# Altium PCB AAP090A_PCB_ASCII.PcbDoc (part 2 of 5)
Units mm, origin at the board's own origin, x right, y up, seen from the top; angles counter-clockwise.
Board outline 160 x 130 mm, 4 copper layers (Top Layer, Signal Layer 1, Signal Layer 2, Bottom Layer), stack 1.567 mm thick; 507 components, 275 nets, 1462 pads, 1041 vias.
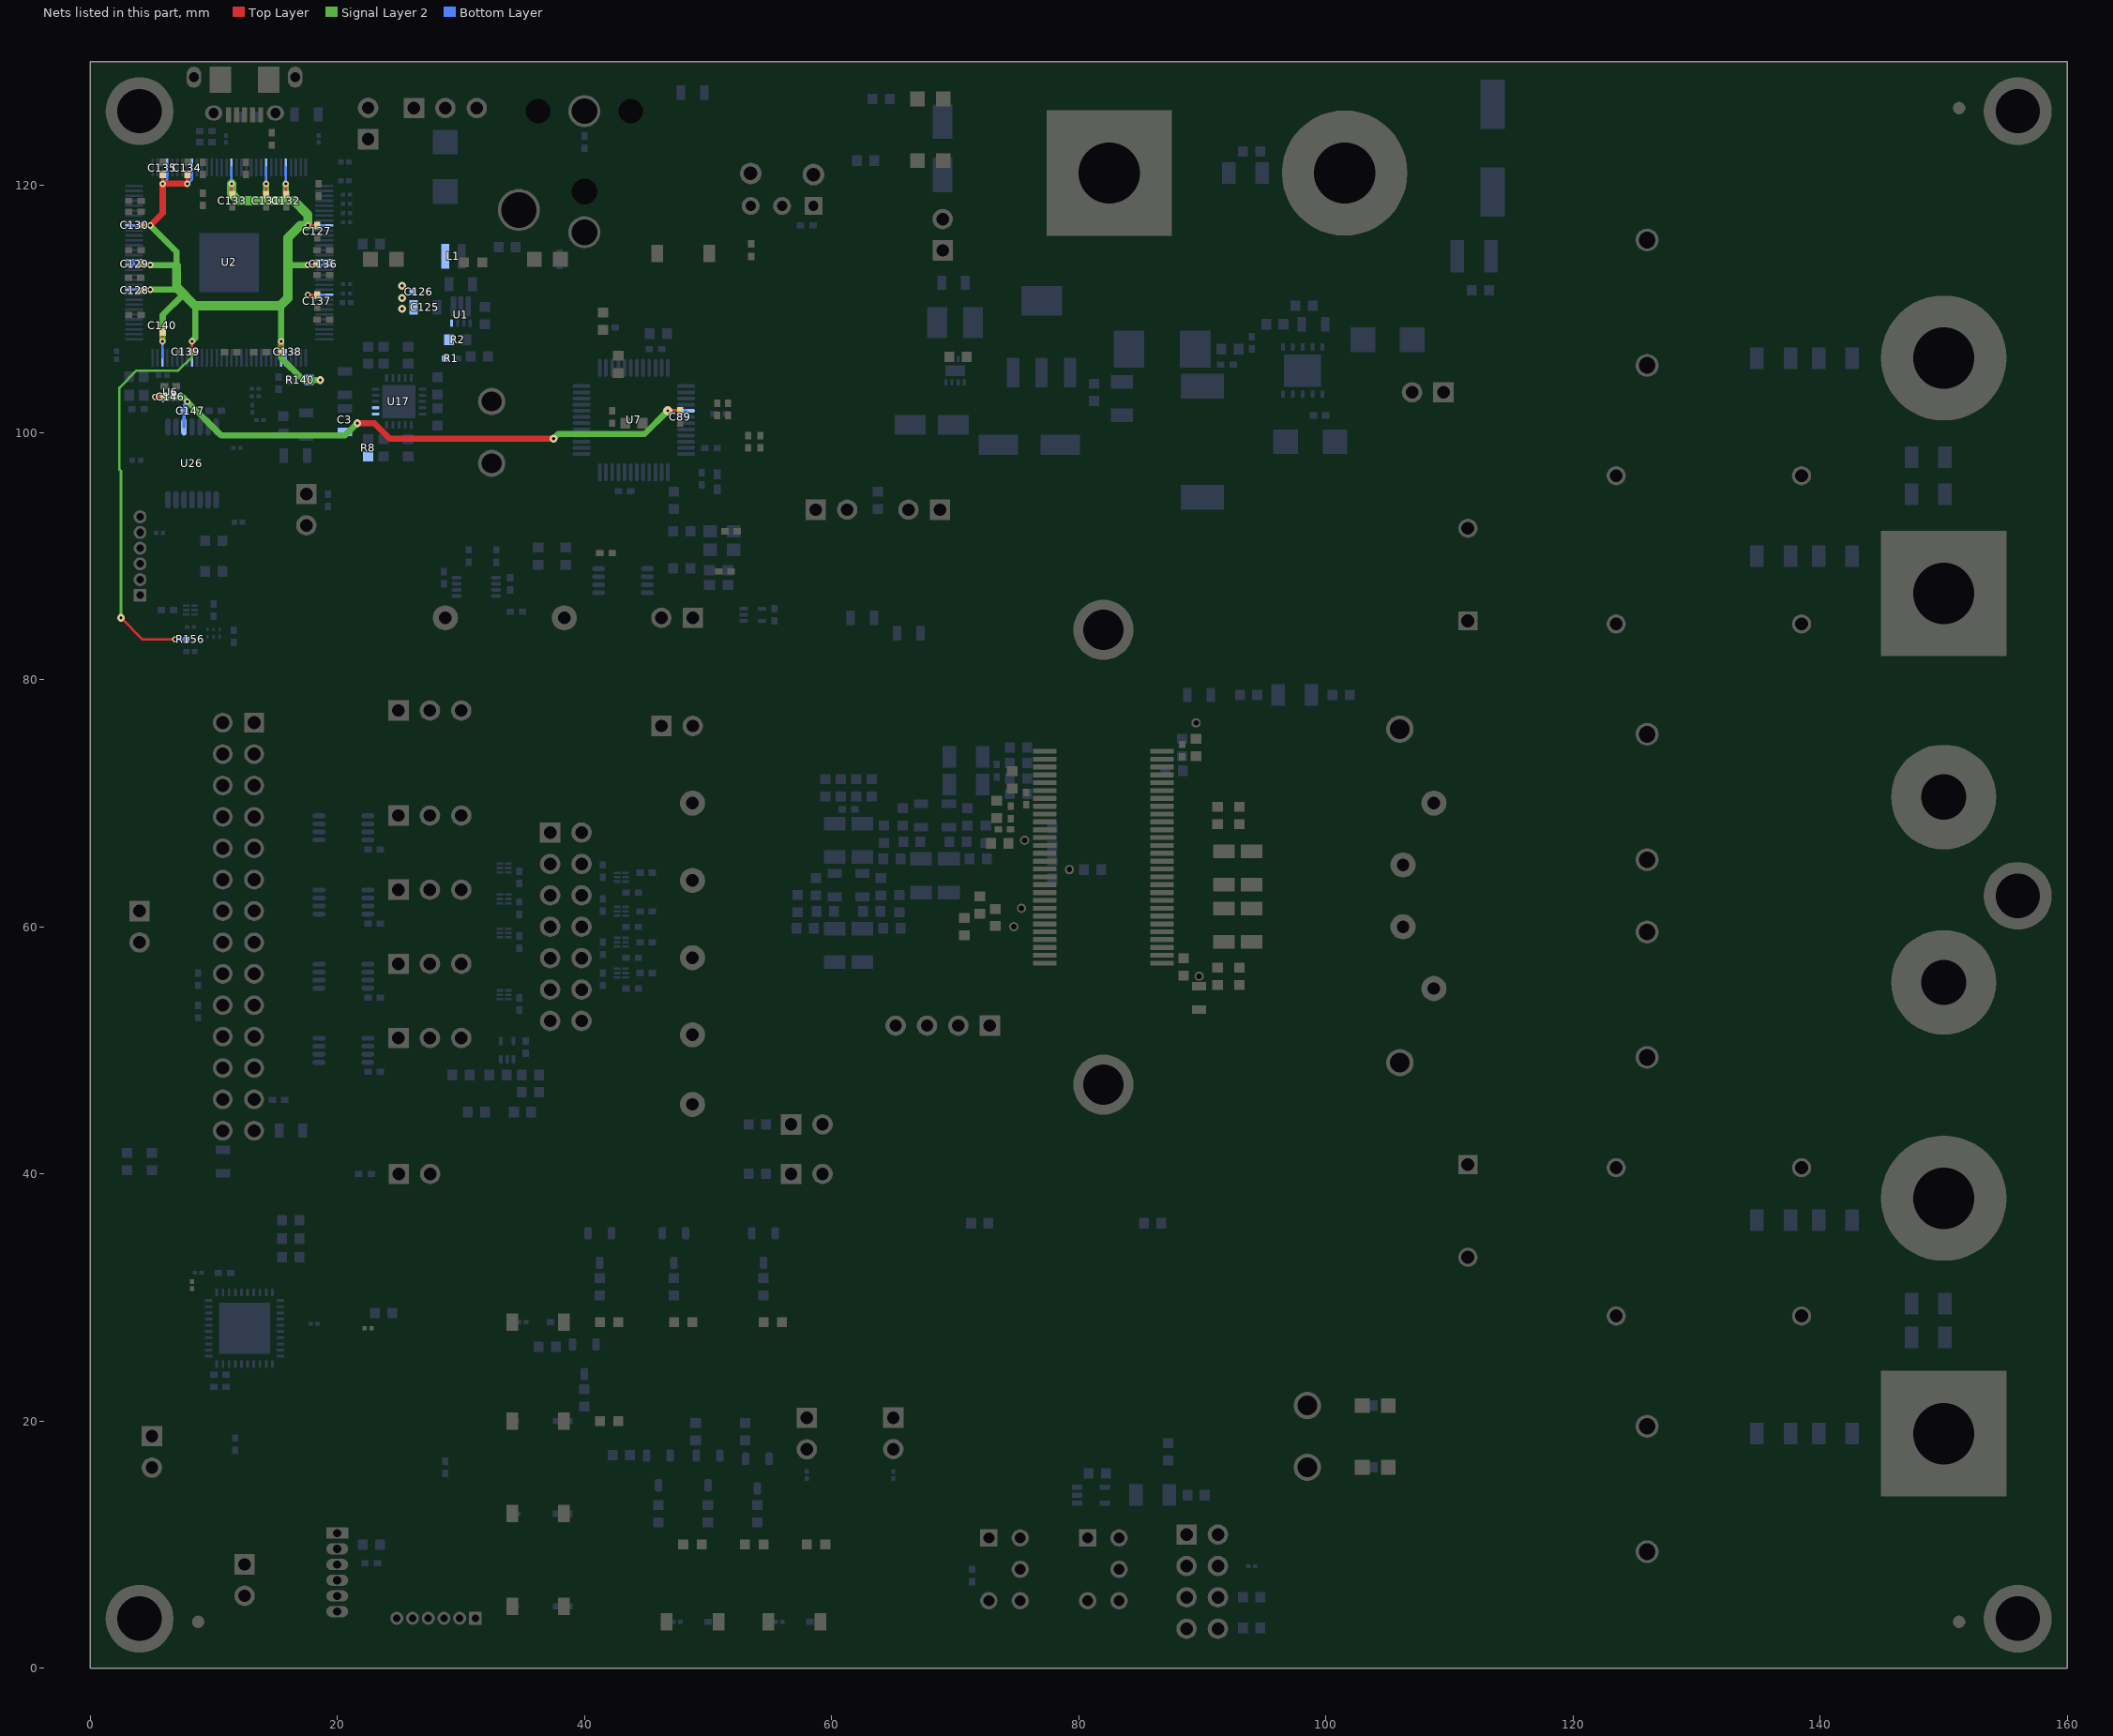
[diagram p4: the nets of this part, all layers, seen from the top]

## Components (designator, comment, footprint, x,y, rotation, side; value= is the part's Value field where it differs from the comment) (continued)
R159 "RC0805JR-070RL" 0805_KTR 17.5,100.625 r270 bottom
R160 "DNP" 0201L 20.75,112 r180 bottom
R161 "DNP" 0201L 20.75,111.25 r180 bottom
R162 "DNP" 0201L 13.375,103.545 r180 bottom
R163 "DNP" 0201L 13.375,102.92 r180 bottom
R164 "RC0805JR-070RL" 0805_KTR 16.625,98.125 r180 bottom
R165 "ERJ-3GEY0R00V" 0603L 88.375,74.5 r90 bottom
R166 "DNP" 0603L 87.75,72.625 r0 bottom
R167 "DNP" 0603L 15.625,100.625 r270 bottom
R168 "ERJ-3GEY0R00V" 0603L 35,45 r0 bottom
R169 "ERJ-3GEY0R00V" 0603L 38.5,90 r90 bottom
R170 "ERJ-3GEY0R00V" 0603L 36.25,90 r90 bottom
S1 "DAC MUTE" SW_200USP1T1A1M2 74,8 r0 top
S2 "SPDIF-RESET" SW_TL1015AF160QG 48,114.5 r0 top
S3 "AMP RESET" SW_200USP1T1A1M2 82,8 r0 top
S4 "MUTE" SW_TL1015AF160QG 36.25,20 r180 top
S5 "VOL UP" SW_TL1015AF160QG 36.25,12.5 r180 top
S6 "VOL DN" SW_TL1015AF160QG 36.25,5 r180 top
S7 "PROGRAM SEL" SW_TL1015AF160QG 57,3.75 r180 top
S8 "LOAD" SW_TL1015AF160QG 48.75,3.75 r180 top
S9 "INPUT" SW_TL1015AF160QG 36.25,28 r180 top
SH1 "SNT-100-BK-G" SNT-100-BK-G#1 69,116 r90 bottom
SH2 "SNT-100-BK-G" SNT-100-BK-G#1 30,126.25 r180 bottom
SH3 "SNT-100-BK-G" SNT-100-BK-G#1 60,93.75 r180 bottom
SH4 "SNT-100-BK-G" SNT-100-BK-G#1 108.25,103.25 r180 bottom
SH5 "SNT-100-BK-G" SNT-100-BK-G#1 67.5,93.75 r180 bottom
SH6 "SNT-100-BK-G" SNT-100-BK-G#2 22.5,125 r90 top
SH7 "SNT-100-BK-G" SNT-100-BK-G#2 47.5,76.25 r0 top
SH8 "SNT-100-BK-G" SNT-100-BK-G#2 26.25,63 r0 top
SH9 "SNT-100-BK-G" SNT-100-BK-G#2 26.25,51 r0 top
SH10 "SNT-100-BK-G" SNT-100-BK-G#2 48.75,86.25 r270 top
SH11 "SNT-100-BK-G" SNT-100-BK-G#2 26.25,69 r0 top
SH12 "SNT-100-BK-G" SNT-100-BK-G#2 26.25,57 r0 top
SH13 "SNT-100-BK-G" SNT-100-BK-G#2 59.25,45.25 r90 top
SH14 "SNT-100-BK-G" SNT-100-BK-G#2 59.25,38.75 r90 top
SH15 "SNT-100-BK-G" SNT-100-BK-G#2 11.25,8.5 r0 top
SH16 "SNT-100-BK-G" SNT-100-BK-G#2 16.25,95 r0 top
SH17 "SNT-100-BK-G" SNT-100-BK-G#2 3.75,18.75 r0 top
SH18 "SNT-100-BK-G" SNT-100-BK-G#2 90,8.25 r0 top
SH19 "SNT-100-BK-G" SNT-100-BK-G#2 26.25,40 r0 top
SH20 "SNT-100-BK-G" SNT-100-BK-G#2 26.25,77.5 r0 top
SH21 "SNT-100-BK-G" SNT-100-BK-G#2 58,19 r90 top
SH22 "SNT-100-BK-G" SNT-100-BK-G#2 65,19 r90 top
TP1 "SDIN" Keystone5003 48.75,63.75 r0 top
TP2 "MCLK" Keystone5003 48.75,70 r0 top
TP3 "BCLK" Keystone5003 48.75,57.5 r0 top
TP4 "LRCK" Keystone5003 48.75,51.25 r0 top
TP5 "5V-IN" Keystone5010 32.5,102.5 r0 top
TP6 "GND" Keystone5011 32.5,97.5 r0 top locked
TP7 "PVDD_B" Keystone5128 106,76 r180 bottom
TP8 "PVDD_A" Keystone5128 106,49 r180 bottom
TP9 "GVDD_A" TP_H045P075 75.625,67 r90 bottom
TP10 "GVDD_B" TP_H045P075 89.75,56 r90 bottom
TP11 "AVDD" TP_H045P075 74.75,60 r90 bottom
TP12 "DAC-AVDD" TP_H045P075 89.5,76.5 r90 bottom
TP13 "DVDD" TP_H045P075 75.375,61.5 r90 bottom
TP14 "OC-ADJ" TP_H045P075 79.25,64.625 r90 bottom
TP15 "CLIP_OTW" Keystone5128 98.5,21.25 r90 top
TP16 "FAULT" Keystone5128 98.5,16.25 r90 top
TP17 "OUTA+" Keystone5003 108.75,70 r0 top
TP18 "OUTA-" Keystone5003 106.25,65 r0 top
TP19 "OUTB+" Keystone5003 106.25,60 r0 top
TP20 "OUTB-" Keystone5003 108.75,55 r0 top
TP21 "SCL" Keystone5003 28.75,85 r90 top
TP22 "SDA" Keystone5003 38.375,85 r90 top
TP23 "GND" Keystone5001 48.75,45.625 r90 top
U1 "TPS62085RLTR" RLT0007A 30,109.75 r90 bottom
U2 "XEF216-512-TQ128-C20" TQFP-128 11.25,113.75 r0 bottom locked
U3 "TCA9406DCUR" DCU0008A_N 31.25,87.5 r180 bottom
U4 "SPDIF-IN" PLR135_T10 56,123 r0 top
U5 "TPS3802K33DCKR" DCK0005A_N 81,14 r0 bottom
U6 "SN74AVC2T244DQMR" DQM0008A 6.5,103.25 r270 bottom
U7 "SRC4392IPFBR" PFB0048A_N 44,101 r270 bottom locked
U8 "TAS3251DKQR" DKQ0056A 82,65.625 r0 top locked
U9 "SN74LVC2G157DCTR" DCT0008A_N 20.5,68 r0 bottom
U10 "LM5010ASD/NOPB" SDC10A 98.125,105 r90 bottom
U11 "SN74LVC2G157DCTR" DCT0008A_N 20.5,62 r0 bottom locked
U12 "MSP430G2955IRHA40R" RHA0040B 12.5,27.5 r0 bottom
U13 "SN74LVC2G157DCTR" DCT0008A_N 20.5,56 r0 bottom
U14 "SN74LVC2G157DCTR" DCT0008A_N 20.5,50 r0 bottom
U15 "LM2940IMP-12/NOPB" MP04A_N 77,107.75 r90 bottom
U16 "TPS62163DSGR" DSG0008A 70,105 r90 bottom
U17 "TPS7A8801RTJR" RTJ0020D 25,102.5 r180 bottom locked
U18 "LVC1G125DSF" DSF0006A 33.5,64.75 r0 bottom
U19 "LVC1G125DSF" DSF0006A 43,64 r0 bottom
U20 "LVC1G125DSF" DSF0006A 33.5,59.5 r0 bottom
U21 "LVC1G125DSF" DSF0006A 43,58.75 r0 bottom
U22 "LVC1G125DSF" DSF0006A 33.5,54.5 r0 bottom
U23 "LVC1G125DSF" DSF0006A 43,56.25 r0 bottom
U24 "LVC1G125DSF" DSF0006A 33.5,62.25 r0 bottom
U25 "LVC1G125DSF" DSF0006A 43,61.25 r0 bottom
U26 "CDCE913PWR" PW0014A_N 8.25,97.5 r270 bottom locked
U27 "LVC1G14" DRL0005A 53.625,85.25 r0 bottom
U28 "LVC1G14" DRL0005A 33.75,50 r90 bottom
U29 "SN74LVC2G07DSFR" DSF0006A 8.125,85.625 r180 bottom
U30 "TPS3897ADRYR" DRY0006A 10,83.75 r90 bottom
U31 "SN74LVC2G157DCTR" DCT0008A_N 43.125,88 r180 bottom
Y1 "ASTMLPA-24.000MHZ-EJ-E-T" Abracon_ASTMLPA 3.75,103.75 r0 bottom
Y2 "ASTMHTA-24.576MHZ-AJ-E" Abracon_ASTMLPA 50.875,88.25 r90 bottom
Y3 "TD-22.5792MBD-T" TXC_TD 51.125,91.25 r90 bottom
ZZ1 "These assemblies are ESD sensitive, ESD precautions shall be observed." AssemblyNote 5,145 r0 top
ZZ2 "These assemblies must be clean and free from flux and all contaminants. Use of no clean flux is not acceptable." AssemblyNote 5,143 r0 top
ZZ3 "These assemblies must comply with workmanship standards IPC-A-610 Class 2, unless otherwise specified." AssemblyNote 5,141 r0 top

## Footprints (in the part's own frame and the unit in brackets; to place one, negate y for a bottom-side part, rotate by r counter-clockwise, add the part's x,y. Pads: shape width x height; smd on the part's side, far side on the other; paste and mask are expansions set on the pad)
0201 [mm] "Data from Kemet datasheet CC101_COM dated 7/28/11"
  rect 0.46x0.42 smd mask+0: 1(-0.33,0) 2(0.33,0)
0201L [mm] "Data from Kemet datasheet CC101_COM dated 7/28/11"
  rect 0.36x0.32 smd mask+0: 1(-0.28,0) 2(0.28,0)
0402 [mm] "0402 from SM-752 data"
  rect 0.8x0.6 smd: 1(-0.6,0) 2(0.6,0)
  silkscreen extent -1.22,-0.52 1.22,0.52
0402L [mm] "0402 from SM-752 data"
  rect 0.6x0.5 smd: 1(-0.5,0) 2(0.5,0)
0603L [mm] "0603 from SM-752 data"
  rect 0.8x0.85 smd: 1(-0.7,0) 2(0.7,0)
  silkscreen extent -0.07,-0.33 0.07,0.33
0805_KTR [mm] "ROHM"
  rect 0.7x1.15 smd: 1(-0.95,0) 2(0.95,0)
  silkscreen extent -0.35,-0.7 0.35,0.7
1206_180L [mm] "1206_180"
  rect 1.1x1.75 smd: 1(-1.35,0) 2(1.35,0)
  silkscreen extent -0.4,-0.77 0.4,0.77
1206L [mm] "1206 from SM-752 data"
  rect 1.1x1.75 smd: 1(-1.35,0) 2(1.35,0)
  silkscreen extent -0.4,-0.77 0.4,0.77
1210_210L [mm] "1210"
  rect 1.1x2.6 smd: 1(-1.35,0) 2(1.35,0)
  silkscreen extent -0.4,-1.2 0.4,1.2
Abracon_ASTMLPA [mm] "SMD, 4-Leads, Body 2x1.6mm"
  rect 0.8x0.9 smd: 1(-0.6,0.75) 2(-0.6,-0.75) 3(0.6,-0.75) 4(0.6,0.75)
  silkscreen extent -1.46,0.74 -1.34,0.86
Advanced_ATS078036036-TI1OP-1099-C1-R1 [mm] "Heat Sink, Body 36x78mm"
  round 4.875 hole 3.25: 1(-18.4,0) 2(18.4,0)
"APM_RM3X8MM 2701" [mm] "Screw, Dia 6.7mm, Length 8mm, TH"
  round 5.5 hole 3.6: ""(0,0)
  silkscreen extent -3.35,-3.35 3.35,3.35
AssemblyNote [mm] "Assembly Note"
B32652_1800x900x1750 [mm] "TH, 2-Leads, Body 18x9mm, Pin Spacing 15mm"
  round 1.55 hole 1.05: 1(-7.5,0) 2(7.5,0)
  silkscreen extent -9,-4.5 9,4.5
CONN_22112042 [mm] "Molex"
  rect 1.65x1.65 hole 1.016 mask+0: 1(-3.81,0)
  round 1.65 hole 1.016 mask+0: 2(-1.27,0) 3(1.27,0) 4(3.81,0)
  silkscreen extent -5.08,-3.25 5.08,3.1
CONN_PEC04DAAN [mm] "SULLINS"
  rect 1.65x1.65 hole 1.016 mask+0: 1(-3.81,-1.27)
  round 1.65 hole 1.016 mask+0: 2(-3.81,1.27) 3(-1.27,-1.27) 4(-1.27,1.27) 5(1.27,-1.27) 6(1.27,1.27) 7(3.81,-1.27) 8(3.81,1.27)
  silkscreen extent -6.18,-2.6 5.08,2.54
CONN_SBH11-PBPC-D07-ST-BK [mm] "Sullins recommended land pattern"
  rect 1.65x1.65 hole 1.016 mask+0: 1(-7.62,-1.27)
  round 1.65 hole 1.016 mask+0: 2(-7.62,1.27) 3(-5.08,-1.27) 4(-5.08,1.27) 5(-2.54,-1.27) 6(-2.54,1.27) 7(0,-1.27) 8(0,1.27) 9(2.54,-1.27) 10(2.54,1.27) 11(5.08,-1.27) 12(5.08,1.27) 13(7.62,-1.27) 14(7.62,1.27)
  silkscreen extent -12.64,-5.08 12.64,4.7
CONN_SSW-114-01-G-D [mm] "SAMTEC"
  rect 1.6x1.6 hole 1.04: 1(16.51,-1.27)
  round 1.6 hole 1.04: 2(16.51,1.27) 3(13.97,-1.27) 4(13.97,1.27) 5(11.43,-1.27) 6(11.43,1.27) 7(8.89,-1.27) 8(8.89,1.27) 9(6.35,-1.27) 10(6.35,1.27) 11(3.81,-1.27) 12(3.81,1.27) 13(1.27,-1.27) 14(1.27,1.27) 15(-1.27,-1.27) 16(-1.27,1.27) 17(-3.81,-1.27) 18(-3.81,1.27) 19(-6.35,-1.27) 20(-6.35,1.27) 21(-8.89,-1.27) 22(-8.89,1.27) 23(-11.43,-1.27) 24(-11.43,1.27) 25(-13.97,-1.27) 26(-13.97,1.27) 27(-16.51,-1.27) 28(-16.51,1.27)
  silkscreen extent -17.8,-3.9 17.8,2.5
CONN_USB_DX4R205JJA [mm] "Connecctor, USB-AB, 5 Pos"
  rect 0.4x1.2 smd mask+0: 1(-1.3,4.3) 2(-0.65,4.3) 3(0,4.3) 4(0.65,4.3) 5(1.3,4.3)
  oval 1.4x1.2 hole 0.8 slot 1 at 0 deg: 6(-2.5,4.15) 7(2.5,4.15)
  oval 1.2x1.7 hole 0.8 slot 1.3 at 90 deg: 8(-4.1,1.25) 9(4.1,1.25)
  rect 1.73x2.1 smd: M1(-1.96,1.45) M2(1.96,1.45)
  silkscreen extent -3.76,2.4 3.76,4.35
DCK0005A_N [mm] "SOT353, 5-Leads, Body 2x1.3mm, Pitch 0.65mm, Lead Span 2.1mm, IPC Medium Density"
  rrect25% 0.85x0.4 smd: 1(-1.125,0.65) 2(-1.125,0) 3(-1.125,-0.65) 4(1.125,-0.65) 5(1.125,0.65)
  silkscreen extent -1.48,-1.02 0.55,1.1
DCT0008A_N [mm] "TSOP, 8-Leads, Body 3x2.8mm, Pitch 0.65mm, IPC Medium Density"
  oval 1.05x0.4 smd: 1(-1.975,0.975) 2(-1.975,0.325) 3(-1.975,-0.325) 4(-1.975,-0.975) 5(1.975,-0.975) 6(1.975,-0.325) 7(1.975,0.325) 8(1.975,0.975)
  silkscreen extent -2.32,-1.57 1.4,1.58
DCU0008A_N [mm] "TSSOP, 8-Leads, Body 2x2.3mm, Pitch 0.5mm, IPC Medium Density"
  oval 0.8x0.3 smd: 1(-1.6,0.75) 2(-1.6,0.25) 3(-1.6,-0.25) 4(-1.6,-0.75) 5(1.6,-0.75) 6(1.6,-0.25) 7(1.6,0.25) 8(1.6,0.75)
  silkscreen extent -1.05,-1.05 0.38,1.05
DKQ0056A [mm] "SOP, 56-Leads, Body 18.415x7.49mm, Pitch 0.635mm"
  rrect25% 1.9x0.4 smd: 1(-4.75,8.572) 2(-4.75,7.938) 3(-4.75,7.302) 4(-4.75,6.667) 5(-4.75,6.032) 6(-4.75,5.397) 7(-4.75,4.763) 8(-4.75,4.127) 9(-4.75,3.492) 10(-4.75,2.857) 11(-4.75,2.222) 12(-4.75,1.587) 13(-4.75,0.953) 14(-4.75,0.318) 15(-4.75,-0.318) 16(-4.75,-0.953) 17(-4.75,-1.587) 18(-4.75,-2.222) 19(-4.75,-2.857) 20(-4.75,-3.492) 21(-4.75,-4.127) 22(-4.75,-4.763) 23(-4.75,-5.397) 24(-4.75,-6.032) 25(-4.75,-6.667) 26(-4.75,-7.302) 27(-4.75,-7.938) 28(-4.75,-8.572) 29(4.75,-8.572) 30(4.75,-7.938) 31(4.75,-7.302) 32(4.75,-6.667) 33(4.75,-6.032) 34(4.75,-5.397) 35(4.75,-4.763) 36(4.75,-4.127) 37(4.75,-3.492) 38(4.75,-2.857) 39(4.75,-2.222) 40(4.75,-1.587) 41(4.75,-0.953) 42(4.75,-0.318) 43(4.75,0.318) 44(4.75,0.953) 45(4.75,1.587) 46(4.75,2.222) 47(4.75,2.857) 48(4.75,3.492) 49(4.75,4.127) 50(4.75,4.763) 51(4.75,5.397) 52(4.75,6.032) 53(4.75,6.667) 54(4.75,7.302) 55(4.75,7.938) 56(4.75,8.572)
  silkscreen extent -5.55,-9.2 3.74,9.2
DQM0008A [mm] "TI"
  rrect50% 0.7x0.2 smd: 1(-0.45,0.6) 2(-0.45,0.2) 3(-0.45,-0.2) 4(-0.45,-0.6) 5(0.45,-0.6) 6(0.45,-0.2) 7(0.45,0.2) 8(0.45,0.6)
  silkscreen extent -0.72,-1.02 0.72,1.02
DRL0005A [mm] "SOTFL, 5-Flat Leads, Body 1.2x1.6x0.6mm, Pitch 0.5mm, TI recommended"
  rrect33% 0.67x0.3 smd: 1(-0.74,0.5) 2(-0.74,0) 3(-0.74,-0.5) 4(0.74,-0.5) 5(0.74,0.5)
  silkscreen extent -0.9,-0.95 0.5,0.95
DRY0006A [mm] "PSON, 6-Leads, Body 1x1.45mm, Pitch 0.5mm, TI Recommended"
  rect 0.35x0.2 smd: 1(-0.275,0.5)
  rect 0.3x0.2 smd: 2(-0.3,0) 3(-0.3,-0.5) 4(0.3,-0.5) 5(0.3,0) 6(0.3,0.5)
  silkscreen extent -0.5,-0.85 0.2,0.85
DSF0006A [mm] "TI recommended land pattern"
  rect 0.53x0.2 smd paste-0.1 mask+0: 1(-0.34,0.35) 2(-0.34,0) 3(-0.34,-0.35) 4(0.34,-0.35) 5(0.34,0) 6(0.34,0.35)
  silkscreen extent -0.85,0.63 -0.75,0.72
DSG0008A [mm] "SON, 8-Leads, Body 2x2mm, Pitch 0.5mm, Thermal Pad 1.6x0.9mm, TI Recommended"
  rrect40% 0.5x0.25 smd: 1(-0.95,0.75) 2(-0.95,0.25) 3(-0.95,-0.25) 4(-0.95,-0.75) 5(0.95,-0.75) 6(0.95,-0.25) 7(0.95,0.25) 8(0.95,0.75)
  rrect11% 0.9x1.6 smd paste-0.45: 9(0,0)
  silkscreen extent -1.07,-1.15 1.07,1.15
FC_1800x3550 [mm] "TH, 2-Leads, Dia 18mm, Lead Spacing 7.5mm"
  rect 1.55x1.55 hole 1.05: 1(-3.75,0)
  round 1.55 hole 1.05: 2(3.75,0)
  silkscreen extent -9.25,-9.25 9.25,9.25
FCC_disclaimer [mm]
Fiducial10-20 [mm]
  round 1 smd mask+0: 1(0,0)
  Top Layer keep-out circle w1.178: c0,0 r0.5
HARWIN_S1911-46R [mm] "HARWIN"
  rect 2.48x3 smd mask+0: 1(-2.69,0) 2(2.69,0)
  silkscreen extent -0.5,-1.5 0.5,1.5
Keystone5001 [mil] "For Keystone 500x miniature loop terminals"
  round 80 hole 40: 1(0,0)
  silkscreen extent -52,-52 52,52
Keystone5003 [mil] "For Keystone 500x miniature loop terminals"
  round 80 hole 40: 1(0,0)
  silkscreen extent -52,-52 52,52
Keystone5010 [mil] "Keystone Multipurpose loops"
  round 87 hole 63: 1(0,0)
  silkscreen extent -70,-70 70,70
Keystone5011 [mil] "Keystone Multipurpose loops"
  round 87 hole 63: 1(0,0)
  silkscreen extent -70,-70 70,70
Keystone5128 [mil] "Keystone Multipurpose loops"
  round 87 hole 63: 1(0,0)
  silkscreen extent -70,-70 70,70
Keystone24438 [mil] "Standoff, Aluminium, M3x0.5mm, L 25 mm"
  round 1 on Mech4: 0(0,0)
Keystone_971 [mm] "PC Mount Phono Jack-Red, TH"
  round 2.6 hole 2.08: 1(0,0) 3(9.8,0)
  round 3.4 hole 2.87: 4(8,-5.3)
  round 0 hole 1.98 unplated: M1(0,3.745) M2(0,-3.745)
  round 0 hole 2.08 unplated: M3(6.5,0)
  silkscreen extent -3.99,-5.01 10.03,5.01
Keystone_7007 [mm] "KEYSTONE"
  round 8.5 hole 3.658: 1(0,0)
  silkscreen extent -4.8,-4.8 4.8,4.8
"LB Q39G_BLUE" [mm] "OSRAM"
  rect 0.8x0.8 smd: 1(-0.75,0) 2(0.75,0)
  silkscreen extent 1.3,-0.5 1.52,0.5
LED_LTST-C170_Red [mm] "LITE-ON"
  rect 1.2x1.2 smd: 1(-1.05,0) 2(1.05,0)
  silkscreen extent -1.6,-1 2.2,1
LED_LTST-C171 [mm] "LITE-ON"
  rect 1.2x1.2 smd: 1(-1.05,0) 2(1.05,0)
  silkscreen extent -1.6,-1 2.2,1
LED_LTST-C190_Red [mm] "Lite-On"
  rect 0.8x0.8 smd: 1(-0.75,0) 2(0.75,0)
  silkscreen extent -1.1,-0.8 1.8,0.8
LTST-C170KFKT_Orange [mm] "LITE-ON"
  rect 1.2x1.2 smd: 1(-1.05,0) 2(1.05,0)
  silkscreen extent -1.6,-1 2.2,1
LTST-C170TBKT_Blue [mm] "LITE-ON"
  rect 1.2x1.2 smd: 1(-1.05,0) 2(1.05,0)
  silkscreen extent -1.6,-1 2.2,1
MA5173 [mm] "TH, 2-Leads, Body 28.6x12.3mm, Pin Spacing 10.15mm"
  round 1.85 hole 1.35: 1(-5.075,0) 2(5.075,0)
  silkscreen extent -6.15,-14.3 6.15,14.3
Mill-Max_851-XX-006-10-001000 [mil] "Mill-Max"
  rect 36x70 hole 26: 1(125,0)
  oval 36x70 hole 26: 2(75,0) 3(25,0) 4(-25,0) 5(-75,0) 6(-125,0)
  silkscreen extent -162,-50 177,50
MP04A_N [mm] "SOT223, 4-Leads, Body 6.5x3.5mm, Pitch 2.3mm, Lead Span 7mm, IPC Medium Density"
  rect 2.4x1 smd: 1(-2.9,2.3) 2(-2.9,0) 3(-2.9,-2.3)
  rect 2.4x3.3 smd: 4(2.9,0)
  silkscreen extent -3.02,-3.35 1.4,3.48
Pb-Free_Overlay_Medium [mm]
  silkscreen extent -2.41,-2.41 2.41,2.41
PBC03SAAN [mm] "Sullins 100mil, 1x3, 230 mil above insulator"
  rect 1.65x1.65 hole 1.016: 1(-2.54,0)
  round 1.65 hole 1.016: 2(0,0) 3(2.54,0)
  silkscreen extent -3.81,-1.27 3.81,1.27
PFB0048A_N [mm] "Thin QFP, 48-Leads, Body 7x7mm, Pitch 0.5mm, IPC Medium Density"
  oval 1.45x0.3 smd: 1(-4.225,2.75) 2(-4.225,2.25) 3(-4.225,1.75) 4(-4.225,1.25) 5(-4.225,0.75) 6(-4.225,0.25) 7(-4.225,-0.25) 8(-4.225,-0.75) 9(-4.225,-1.25) 10(-4.225,-1.75) 11(-4.225,-2.25) 12(-4.225,-2.75) 25(4.225,-2.75) 26(4.225,-2.25) 27(4.225,-1.75) 28(4.225,-1.25) 29(4.225,-0.75) 30(4.225,-0.25) 31(4.225,0.25) 32(4.225,0.75) 33(4.225,1.25) 34(4.225,1.75) 35(4.225,2.25) 36(4.225,2.75)
  oval 0.3x1.45 smd: 13(-2.75,-4.225) 14(-2.25,-4.225) 15(-1.75,-4.225) 16(-1.25,-4.225) 17(-0.75,-4.225) 18(-0.25,-4.225) 19(0.25,-4.225) 20(0.75,-4.225) 21(1.25,-4.225) 22(1.75,-4.225) 23(2.25,-4.225) 24(2.75,-4.225) 37(2.75,4.225) 38(2.25,4.225) 39(1.75,4.225) 40(1.25,4.225) 41(0.75,4.225) 42(0.25,4.225) 43(-0.25,4.225) 44(-0.75,4.225) 45(-1.25,4.225) 46(-1.75,4.225) 47(-2.25,4.225) 48(-2.75,4.225)
  silkscreen extent -4.17,-2.75 2.75,3.57
PLR135_T10 [mm] "EVERLIGHT"
  rect 1.45x1.45 hole 0.813: 1(2.54,-4.67)
  round 1.45 hole 0.813: 2(0,-4.67) 3(-2.54,-4.67)
  round 1.75 hole 1.092: 4(2.54,-2.13) 5(-2.54,-2.04)
  silkscreen extent -5.05,-6.93 5.05,6.95
Pomona_6883 [mil] "Dual Binding Posts with Base, 2x1, TH"
  rect 400x400 hole 195: 1(-375,0)
  round 400 hole 195: 2(375,0)
  silkscreen extent -690,-344 690,315
PW0014A_N [mm] "TSOP, 14-Leads, Body 5x4.4mm, Pitch 0.65mm, IPC Medium Density"
  oval 1.4x0.45 smd: 1(-2.95,1.95) 2(-2.95,1.3) 3(-2.95,0.65) 4(-2.95,0) 5(-2.95,-0.65) 6(-2.95,-1.3) 7(-2.95,-1.95) 8(2.95,-1.95) 9(2.95,-1.3) 10(2.95,-0.65) 11(2.95,0) 12(2.95,0.65) 13(2.95,1.3) 14(2.95,1.95)
  silkscreen extent -3.4,-2.55 1.85,2.55
RHA0040B [mm] "QFN, 40-Leads, Body 6x6mm, Pitch 0.5mm, Thermal Pad 4.15 x 4.15mm, TI Recommended"
  rrect45% 0.6x0.22 smd mask+0: 1(-2.9,2.25) 2(-2.9,1.75) 3(-2.9,1.25) 4(-2.9,0.75) 5(-2.9,0.25) 6(-2.9,-0.25) 7(-2.9,-0.75) 8(-2.9,-1.25) 9(-2.9,-1.75) 10(-2.9,-2.25) 21(2.9,-2.25) 22(2.9,-1.75) 23(2.9,-1.25) 24(2.9,-0.75) 25(2.9,-0.25) 26(2.9,0.25) 27(2.9,0.75) 28(2.9,1.25) 29(2.9,1.75) 30(2.9,2.25)
  rrect45% 0.22x0.6 smd mask+0: 11(-2.25,-2.9) 12(-1.75,-2.9) 13(-1.25,-2.9) 14(-0.75,-2.9) 15(-0.25,-2.9) 16(0.25,-2.9) 17(0.75,-2.9) 18(1.25,-2.9) 19(1.75,-2.9) 20(2.25,-2.9) 31(2.25,2.9) 32(1.75,2.9) 33(1.25,2.9) 34(0.75,2.9) 35(0.25,2.9) 36(-0.25,2.9) 37(-0.75,2.9) 38(-1.25,2.9) 39(-1.75,2.9) 40(-2.25,2.9)
  rrect9% 1.17x1.17 on Bottom Paste: 41(-1.37,-1.37) 41(-1.37,0) 41(-1.37,1.37) 41(0,-1.37) 41(0,0) 41(0,1.37) 41(1.37,-1.37) 41(1.37,0) 41(1.37,1.37)
  rrect2% 4.15x4.15 smd paste-2.1: 41(0,0)
  silkscreen extent -3.22,-3.22 3.22,3.22
RLT0007A [mm] "TI"
  rect 0.6x0.25 smd paste-0.2: 1(-0.9,0.75)
  oval 0.6x0.25 smd paste-0.2: 2(-0.9,0.25) 3(-0.9,-0.25) 4(-0.9,-0.75)
  rect 1.64x0.44 smd paste-0.22 mask+0: 5(0.45,-0.6) 6(0.45,0) 7(0.45,0.6)
  silkscreen extent -1.1,-1.15 1.1,1.15
RTJ0020D [mm] "QFN, 20-Leads, Body 4x4mm, Pitch 0.5mm, Thermal Pad 2.7x2.7mm, TI Recommended"
  rrect42% 0.6x0.24 smd: 1(-1.9,1) 2(-1.9,0.5) 3(-1.9,0) 4(-1.9,-0.5) 5(-1.9,-1) 11(1.9,-1) 12(1.9,-0.5) 13(1.9,0) 14(1.9,0.5) 15(1.9,1)
  rrect42% 0.24x0.6 smd: 6(-1,-1.9) 7(-0.5,-1.9) 8(0,-1.9) 9(0.5,-1.9) 10(1,-1.9) 16(1,1.9) 17(0.5,1.9) 18(0,1.9) 19(-0.5,1.9) 20(-1,1.9)
  rrect8% 1.19x1.19 on Bottom Paste: 21(-0.695,-0.695) 21(-0.695,0.695) 21(0.695,-0.695) 21(0.695,0.695)
  rrect4% 2.7x2.7 smd paste-1.4: 21(0,0)
  silkscreen extent -2.22,-2.22 2.23,2.22
SDC10A [mm] "SON, 10-Leads, Body 4x4 mm, Pitch 0.8mm, NSC Recommended"
  rect 0.6x0.3 smd paste-0.15 mask+0: 1(-1.9,1.6) 2(-1.9,0.8) 3(-1.9,0) 4(-1.9,-0.8) 5(-1.9,-1.6) 6(1.9,-1.6) 7(1.9,-0.8) 8(1.9,0) 9(1.9,0.8) 10(1.9,1.6)
  rect 2.6x3 smd paste-1.3 mask+0: 11(0,0)
  silkscreen extent -3.02,-2.2 2.35,2.23
SM_RADIAL_B [mm] "4 x 5.8mm:  Panasonic B"
  rect 2.5x1.6 smd: 1(-1.75,0) 2(1.75,0)
  silkscreen extent -2.24,-2.25 2.25,2.25
SM_RADIAL_C [mm] "5 x 5.8mm:  Panasonic C"
  rect 2.8x1.6 smd: 1(-2.15,0) 2(2.15,0)
  silkscreen extent -2.75,-2.75 2.75,2.75
SM_RADIAL_D [mm] "6.3 x 5.8mm:  Panasonic D"
  rect 3.2x1.6 smd: 1(-2.5,0) 2(2.5,0)
  silkscreen extent -3.4,-3.4 3.4,3.4
SM_RADIAL_F [mm] "8 x 10.2mm:  Panasonic F"
  rect 4x2 smd: 1(-3.55,0) 2(3.55,0)
  silkscreen extent -4.25,-4.25 4.25,4.25
SMA [mm] "Molded Diode, 2-Leads, Body 4.3x2.6mm, IPC Medium Density, based on OnSemi component dimensions and land pattern"
  rect 2x2 smd: 1(-2,0) 2(2,0)
  silkscreen extent -3.66,-1.57 2.79,1.57
SNT-100-BK-G#1 [mil] "Samtec STEP model"
  round 1 on Mech4: 0(0,0)
SNT-100-BK-G#2 [mil] "Samtec STEP model"
  round 1 on Mech3: 0(0,0)
SOT-23 [mm] "SOT23, 3-Leads, Body 2.9x1.3mm, Pitch 0.95mm, Lead Span 2.5mm, IPC Medium Density"
  rrect50% 1x0.6 smd: 1(-1.2,0.95) 2(-1.2,-0.95) 3(1.2,0)
  silkscreen extent -1.62,-1.5 0.7,1.5
SULLINS_LPPB061NGCN-RC [mm] "SULLINS"
  rect 1.05x1.05 hole 0.61: 1(3.175,2.54)
  round 1.05 hole 0.61: 2(1.905,2.54) 3(0.635,2.54) 4(-0.635,2.54) 5(-1.905,2.54) 6(-3.175,2.54)
  silkscreen extent -4,-2.37 4.03,2
Sullins_PBC02SAAN [mm] "Sullins 100mil, 1x2, 230 mil above insulator"
  rect 1.65x1.65 hole 1.016: 1(0,1.27)
  round 1.65 hole 1.016: 2(0,-1.27)
  silkscreen extent -1.37,-2.54 1.27,3.1
SW_200USP1T1A1M2 [mm] "TH, 5-Leads, Body 7x4.5mm, Pitch 2.54mm"
  rect 1.4x1.4 hole 0.9: 1(-1.27,2.54)
  round 1.4 hole 0.9: 3(-1.27,-2.54) 4(1.27,2.54) 5(1.27,0) 6(1.27,-2.54)
  silkscreen extent -2.7,-3.63 2.38,3.63
SW_TL1015AF160QG [mm] "E-Switch"
  rect 0.95x1.4 smd: 1(-2.1,0) 2(2.1,0)
  silkscreen extent -2,-1.5 2,1.5
TI_Stacked_Overlay_Small [mm]
TP_H045P075 [mm] "TP_H0.45P0.75"
  round 0.75 hole 0.45: 1(0,0)
TQFP-128 [mm] "TQFP, 128-Leads, Body 14x14mm, Pitch 0.4mm"
  rrect50% 1.45x0.2 smd: 1(-7.7,6.2) 2(-7.7,5.8) 3(-7.7,5.4) 4(-7.7,5) 5(-7.7,4.6) 6(-7.7,4.2) 7(-7.7,3.8) 8(-7.7,3.4) 9(-7.7,3) 10(-7.7,2.6) 11(-7.7,2.2) 12(-7.7,1.8) 13(-7.7,1.4) 14(-7.7,1) 15(-7.7,0.6) 16(-7.7,0.2) 17(-7.7,-0.2) 18(-7.7,-0.6) 19(-7.7,-1) 20(-7.7,-1.4) 21(-7.7,-1.8) 22(-7.7,-2.2) 23(-7.7,-2.6) 24(-7.7,-3) 25(-7.7,-3.4) 26(-7.7,-3.8) 27(-7.7,-4.2) 28(-7.7,-4.6) 29(-7.7,-5) 30(-7.7,-5.4) 31(-7.7,-5.8) 32(-7.7,-6.2) 65(7.7,-6.2) 66(7.7,-5.8) 67(7.7,-5.4) 68(7.7,-5) 69(7.7,-4.6) 70(7.7,-4.2) 71(7.7,-3.8) 72(7.7,-3.4) 73(7.7,-3) 74(7.7,-2.6) 75(7.7,-2.2) 76(7.7,-1.8) 77(7.7,-1.4) 78(7.7,-1) 79(7.7,-0.6) 80(7.7,-0.2) 81(7.7,0.2) 82(7.7,0.6) 83(7.7,1) 84(7.7,1.4) 85(7.7,1.8) 86(7.7,2.2) 87(7.7,2.6) 88(7.7,3) 89(7.7,3.4) 90(7.7,3.8) 91(7.7,4.2) 92(7.7,4.6) 93(7.7,5) 94(7.7,5.4) 95(7.7,5.8) 96(7.7,6.2)
  rrect50% 0.2x1.45 smd: 33(-6.2,-7.7) 34(-5.8,-7.7) 35(-5.4,-7.7) 36(-5,-7.7) 37(-4.6,-7.7) 38(-4.2,-7.7) 39(-3.8,-7.7) 40(-3.4,-7.7) 41(-3,-7.7) 42(-2.6,-7.7) 43(-2.2,-7.7) 44(-1.8,-7.7) 45(-1.4,-7.7) 46(-1,-7.7) 47(-0.6,-7.7) 48(-0.2,-7.7) 49(0.2,-7.7) 50(0.6,-7.7) 51(1,-7.7) 52(1.4,-7.7) 53(1.8,-7.7) 54(2.2,-7.7) 55(2.6,-7.7) 56(3,-7.7) 57(3.4,-7.7) 58(3.8,-7.7) 59(4.2,-7.7) 60(4.6,-7.7) 61(5,-7.7) 62(5.4,-7.7) 63(5.8,-7.7) 64(6.2,-7.7) 97(6.2,7.7) 98(5.8,7.7) 99(5.4,7.7) 100(5,7.7) 101(4.6,7.7) 102(4.2,7.7) 103(3.8,7.7) 104(3.4,7.7) 105(3,7.7) 106(2.6,7.7) 107(2.2,7.7) 108(1.8,7.7) 109(1.4,7.7) 110(1,7.7) 111(0.6,7.7) 112(0.2,7.7) 113(-0.2,7.7) 114(-0.6,7.7) 115(-1,7.7) 116(-1.4,7.7) 117(-1.8,7.7) 118(-2.2,7.7) 119(-2.6,7.7) 120(-3,7.7) 121(-3.4,7.7) 122(-3.8,7.7) 123(-4.2,7.7) 124(-4.6,7.7) 125(-5,7.7) 126(-5.4,7.7) 127(-5.8,7.7) 128(-6.2,7.7)
  rrect2% 4.8x4.8 smd paste-4.8: 129(0,0)
  silkscreen extent -7.1,-7.1 7.1,7.1
TXC_TD [mm] "SMD, 4-Leads, Body 2x2.5mm"
  rect 1x1.1 smd: 1(-0.75,0.95) 2(-0.75,-0.95) 3(0.75,-0.95) 4(0.75,0.95)
  silkscreen extent -1.74,0.89 -1.61,1.01
VLCF4020 [mm] "TDK"
  rect 1.6x2.5 smd: 1(-1.45,0) 2(1.45,0)
  silkscreen extent -0.4,-2.1 0.4,2.1
VLS2012ET [mm] "TDK"
  rect 0.65x2 smd: 1(-0.675,0) 2(0.675,0)
  silkscreen extent -0.15,-1.15 0.15,1.15
WE-PD_1050 [mm] "WERTH"
  rect 2x3.5 smd: 1(-4.5,0) 2(4.5,0)
  silkscreen extent -5,-5 5,5

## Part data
C1 C3 C92 C124 C125: "CAP, CERM, 22 µF, 10 V, +/- 20%, X7R, 0805"
C2 C60 C71 C87 C91 C93: "CAP, CERM, 10 µF, 10 V, +/- 20%, X5R, 0603"
C4 C63 C65 C95 C107: "CAP, CERM, 1 µF, 16 V, +/- 10%, X7R, 0603"
C5 C8 C11 C14: "CAP, CERM, 10 µF, 16 V, +/- 10%, X7R, 1206"
C6 C9 C12 C15: library part GRM1885C1H221JA01D, "CAP, CERM, 220 pF, 50 V,+/- 5%, C0G/NP0, 0603"
C7 C10 C13 C16: library part GRM1885C1H220JA01D, "CAP, CERM, 22 pF, 50 V, +/- 5%, C0G/NP0, 0603"
C17 C27 C37 C40 C45 C54 C58 C74 C80 C99 C100 C101 C102 C127 C128 C129 C130 C131 C132 C133 C134 C135 C136 C137 C138 C139 C140 C143 C144 C145 C146 C147 C148 C149: "CAP, CERM, 0.1uF, 16V, +/-10%, X7R, 0402"
C18 C19 C56 C59 C61 C69 C70 C72 C73 C88 C89 C90 C94 C108 C109 C110 C111 C112 C113 C114 C115 C116 C117 C118 C119 C120 C121 C122 C123 C151 C156: "CAP, CERM, 0.1 µF, 10 V, +/- 10%, X7R, 0402"
C20 C21: "CAP, CERM, 0.1 µF, 16 V, +/- 10%, X7R, 0603"
C22 C36 C44 C64 C84 C96: "CAP, CERM, 0.1 µF, 50 V, +/- 10%, X7R, 0603"
C23: "CAP, CERM, 2.2 µF, 100 V, +/- 10%, X7R, 1210"
C24 C126 C141: "CAP, CERM, 0.1 µF, 16 V, +/- 10%, X7R, 0402"
C25: "CAP, CERM, 0.1 µF, 100 V, +/- 10%, X7R, 0603"
C26: "CAP, CERM, 0.047 µF, 25 V, +/- 10%, X7R, 0402"
C28 C29 C32 C41 C42 C46 C97: "CAP, CERM, 1 µF, 100 V, +/- 10%, X7R, 1206"
C30 C43: library part EEU-FC1H222, "CAP, AL, 2200 µF, 50 V, +/- 20%, 0.023 ohm, TH"
C31: library part EEE-FK1J470P, "CAP, AL, 47 µF, 63 V, +/- 20%, 0.65 ohm, SMD"
C33: "CAP, CERM, 0.01 µF, 100 V, +/- 10%, X7R, 0603"
C34: "CAP, CERM, 5600 pF, 50 V, +/- 10%, X7R, 0603"
C35: "CAP, CERM, 4700 pF, 50 V, +/- 10%, X7R, 0603"
C38: "CAP, CERM, 4.7 µF, 25 V, +/- 10%, X7R, 1206"
C39: library part EEE-FK1C470P, "CAP, AL, 47 µF, 16 V, +/- 20%, 0.36 ohm, SMD"
C47 C67 C79 C81: "CAP, Film, 0.68 µF, 250 V, +/- 5%, TH"
C48 C49 C50 C51 C53 C57 C150: "CAP, CERM, 470 pF, 25 V, +/- 5%, C0G/NP0, 0402"
C52: "CAP, CERM, 2200 pF, 16 V, +/- 10%, X7R, 0603"
C55: "CAP, CERM, 1 µF, 6.3 V,+/- 20%, X5R, 0402"
C62 C106: "CAP, CERM, 1000 pF, 50 V, +/- 5%, C0G/NP0, 0402"
C66 C68 C76 C77: "CAP, CERM, 0.033 µF, 25 V, +/- 10%, X7R, 0603"
C75: "CAP, CERM, 2.2 µF, 10 V, +/- 10%, X5R, 0402"
C78: "CAP, CERM, 0.047 µF, 50 V, +/- 10%, X7R, 0603"
C82: library part GRM155R71C104KA88D, "CAP, CERM, 0.1 µF, 16 V, +/- 10%, X7R, 0402"
C83: "CAP, CERM, 0.47 µF, 25 V, +/- 10%, X7R, 0603"
C85: library part EEE-FK1C100R, "CAP, AL, 10 µF, 16 V, +/- 20%, 1.35 ohm, SMD"
C86: library part EEE-FK0J101UR, "CAP, AL, 100 µF, 6.3 V, +/- 20%, 0.7 ohm, SMD"
C98 C103 C104 C105: library part GRM31CR72A105KA01L, "CAP, CERM, 1 µF, 100 V, +/- 10%, X7R, 1206"
C142: "CAP, CERM, 2.2 µF, 10 V, +/- 10%, X7R, 0603"
C152 C153 C154 C155: library part GRM3195C1H102JA01D, "CAP, CERM, 1000 pF, 50 V, +/- 5%, C0G/NP0, 1206"
D1: library part LTST-C170TBKT, "LED, Blue, SMD"
D2 D5 D6 D7 D8 D15 D16: library part "LB Q39G-L2N2-35-1", "LED, Blue, SMD"
D3 D13 D14: library part LTST-C171GKT, "LED, Green, SMD"
D4: library part LTST-C190CKT, "LED, Red, SMD"
D9: library part LTST-C170KFKT, "LED, Orange, SMD"
D10: library part LTST-C170KRKT, "LED, Red, SMD"
D11: "Diode, Schottky, 100 V, 3 A, SMA"
D12 D17: "Diode, Schottky, 100 V, 1 A, SMA"
FID1 FID2 FID3 FID4 FID5 FID6: "Fiducial mark.  There is nothing to buy or mount."
H1: library part CMP-0078258-2, "Heat Sink, 36x78x36.5mm"
H2 H3 H4 H5 H10: library part "RM3X8MM 2701", "MACHINE SCREW PAN PHILLIPS M3"
H6 H7 H8 H9 H11: library part 24438, "Standoff, Hex,25mm Length, M3, Aluminum"
J1 J2 J11 J14 J16 J19 J20 J26 J27 J29 J31 J32 J33 J35 J37: library part PBC02SAAN, "Header, 100mil, 2x1, Gold, TH"
J3 J4 J6 J7 J8 J30: library part PBC03SAAN, "Header, 100mil, 3x1, Gold, TH"
J5: library part 971, "RCA Jack, Red, R/A, TH"
J9: library part SBH11-PBPC-D07-ST-BK, "Header (shrouded), 100 mil, 7x2, Gold, TH"
J10 J15 J24: library part CMP-0075104-1, "Dual Binding Posts with Base, 2x1, TH"
J12: library part 851-43-006-10-001000, "Receptacle, 50mil, 6x1, Gold, TH"
J13 J21: library part 7007, "Binding Post, BLACK, TH"
J17 J36: library part LPPB061NGCN-RC, "Receptacle, 50mil, 6x1, Gold, R/A, TH"
J18: library part CMP-0074926-1, "Connector, Receptacle, Micro-USB Type AB, R/A, Bottom Mount SMT"
J22: "Header, 100mil, 4x2, Tin, TH"
J23: "Header (friction lock), 100mil, 4x1, Gold, TH"
J25: library part CMP-0075020-1, "JUMPER TIN SMD"
J28: library part CMP-0075444-1, "Receptacle, 100mil, 14x2, Gold, TH"
J34: "Header, 100mil, 2x1, Gold, TH"
L1: "Inductor, Shielded Drum Core, Ferrite, 470 nH, 2 A, 0.059 ohm, SMD"
L2: "Ferrite Bead, 600 ohm @ 100MHz, 2A, 0805"
L3: library part CMP-0062895-1, "Inductor, Shielded, Ferrite, 2.2 uH, 1.72 A, 0.059 ohm, SMD"
L4: "Ferrite Bead, 120 ohm @ 100 MHz, 0.4 A, 0402"
L5 L6 L7 L8: library part MA5173-AE, "Inductor, Toroid, Powdered Iron, 7 µH, 6.5 A, 0.0215 ohm, TH"
L9: "Inductor, Shielded Drum Core, Ferrite, 100 µH, 1.5 A, 0.165 ohm, SMD"
Logo1: library part TI_Logo, "Texas Instrument Corporate Signature"
Logo2: library part Pb-Free
Logo3: library part FCC_disclaimer, "FCC_disclaimer"
Q1 Q2 Q3 Q4 Q5 Q6 Q7: library part "MMBT2222A, Fairchild Semiconductor", "Transistor, NPN, 40 V, 0.15 A, SOT-23"
R1: "RES, 40.2 k, 1%, 0.1 W, AEC-Q200 Grade 0, 0402"
R2: "RES, 1.00 M, 1%, 0.1 W, 0603"
R3: "RES, 162 k, 1%, 0.1 W, 0603"
R4 R32 R59 R64 R65 R88: "RES, 100 k, 1%, 0.1 W, 0603"
R5 R66 R77 R90 R91 R114 R129 R144 R149 R150 R154 R155: "RES, 10.0 k, 1%, 0.05 W, 0201"
R6: "RES, 33.2 k, 1%, 0.1 W, 0603"
R7: "RES, 10.7 k, 1%, 0.1 W, 0603"
R8: "RES, 13.7 k, 1%, 0.1 W, 0603"
R9: "RES, 11.0 k, 1%, 0.1 W, 0603"
R10 R11 R12 R63 R101 R166 R167: library part ERJ-3GEY0R00V, "RES, 0, 5%, 0.1 W, 0603"
R13 R30 R61 R72: "RES, 0, 5%, 0.25 W, 1206"
R14 R28 R33 R68 R73: library part ERJ-6GEY0R00V, "RES, 0, 5%, 0.125 W, 0805"
R15 R35 R70 R96: library part RC0603FR-0718KL, "RES, 18.0 k, 1%, 0.1 W, 0603"
R16: "RES, 33.0, 1%, 0.1 W, 0402"
R17 R18 R21 R24 R43: "RES, 49.9, 1%, 0.063 W, 0402"
R19 R46 R47 R48 R49 R57 R78 R79 R106 R108 R141: "RES, 560, 5%, 0.1 W, 0603"
R20 R23 R84 R110: "RES, 1.00 k, 1%, 0.0625 W, 0402"
R22 R58 R81 R82 R124 R133: "RES, 4.99 k, 1%, 0.063 W, 0402"
R25: library part RMCF0402FT10K0, "RES, 10.0 k, 1%, 0.063 W, AEC-Q200 Grade 0, 0402"
R26 R27 R111: "RES, 0, 5%, 0.063 W, 0402"
R29 R37 R71 R97: library part RC0603FR-072KL, "RES, 2.00 k, 1%, 0.1 W, 0603"
R31 R36 R125 R126 R127 R128 R159 R164: "RES, 0, 5%, 0.125 W, 0805"
R34: "RES, 182 k, 1%, 0.125 W, 0805"
R38 R39 R40 R42 R44 R45 R156: "RES, 25.5 k, 1%, 0.05 W, 0201"
R41 R157: "RES, 47.0 k, 1%, 0.0625 W, 0402"
R50 R51 R52 R53 R105 R107 R109: "RES, 2.00 k, 1%, 0.1 W, 0603"
R54 R55 R62 R99 R100 R102 R103 R104 R112 R113 R130 R131 R132 R134 R135 R165 R168 R169 R170: "RES, 0, 5%, 0.1 W, 0603"
R56: "RES, 8.06 k, 1%, 0.1 W, 0603"
R60: "RES, 3.30 k, 1%, 0.1 W, 0603"
R67 R69 R86 R95 R98: "RES, 499, 1%, 0.1 W, 0603"
R74: "RES, 22.0 k, 1%, 0.1 W, 0603"
R75: "RES, 30.0 k, 1%, 0.1 W, 0603"
R76: "RES, 20.0 k, 1%, 0.1 W, 0603"
R80 R92 R121 R145: "RES, 10.0 k, 1%, 0.1 W, 0402"
R83 R142 R143 R146 R151 R152 R153: "RES, 33.2, 1%, 0.05 W, 0201"
R85: "RES, 1.50 k, 1%, 0.1 W, 0603"
R87 R89 R93 R94: library part ERJ-8RQF3R3V, "RES, 3.30, 1%, 0.25 W, 1206"
R115 R116 R117 R118: "RES, 100 k, 1%, 0.0625 W, 0402"
R119 R120 R122: library part ERJ-2RKF1002X, "RES, 10.0 k, 1%, 0.1 W, 0402"
R123: "RES, 10.0 k, 1%, 0.063 W, AEC-Q200 Grade 0, 0402"
R136 R137 R138 R139: "RES, 47.0 k, 1%, 0.05 W, 0201"
R140: "RES, 4.75, 1%, 0.1 W, 0603"
R147: "RES, 0, 5%, 0.05 W, 0201"
R148: "RES, 43.2, 1%, 0.05 W, 0201"
R158: "RES, 51.0 k, 1%, 0.05 W, 0201"
R160 R161 R162 R163: library part ERJ-1GE0R00C, "RES, 0, 5%, 0.05 W, 0201"
S1 S3: library part 200USP1T1A1M2RE, "Switch, SPDT, On-On, 2 Pos, TH"
S2 S4 S5 S6 S7 S8 S9: library part TL1015AF160QG, "Switch, Tactile, SPST-NO, 0.05A, 12V, SMT"
SH1 SH2 SH3 SH4 SH5 SH6 SH7 SH8 SH9 SH10 SH11 SH12 SH13 SH14 SH15 SH16 SH17 SH18 SH19 SH20 SH21 SH22: "Shunt, 100mil, Gold plated, Black"
TP1 TP2 TP3 TP4 TP17 TP18 TP19 TP20 TP21 TP22: library part 5003, "Test Point, Miniature, Orange, TH"
TP5: library part 5010, "Test Point, Multipurpose, Red, TH"
TP6: library part 5011, "Test Point, Multipurpose, Black, TH"
TP7 TP8 TP15 TP16: library part 5128, "Test Point, Multipurpose, Grey, TH"
TP9 TP10 TP11 TP12 TP13 TP14: library part TP_H0.45P0.75, "Testpoint"
TP23: library part 5001, "Test Point, Miniature, Black, TH"
U1: "3-A Step-Down Converter with Hiccup Short Circuit Protection in 2x2 QFN Package, RLT0007A"
U2: library part CMP-0004936-1, "IC MCU 512KB RAM, 128TQFP"
U3: "TCA9406 Dual Bidirectional 1-MHz I2C-BUS and SMBus Voltage Level-Translator, 1.65 to 3.6 V, -40 to 85 degC, 8-pin US8 (DCU), Green (RoHS & no Sb/Br)"
U4: library part PLR135/T10, "Photolink- Fiber Optic Receiver, TH"
U5: "ULTRA-SMALL SUPPLY VOLTAGE SUPERVISORS, DCK0005A"
U6: "2-BIT UNDIRECTIONAL VOLTAGE-LEVEL TRANSLATOR, DQM0008A (X2SON-8)"
U7: "216 SPS High-end Combo Sample Rate Converter, 144dB, 1.8 / 3.3V, -40 to 85 degC, 48-Pin TQFP (PFB), Green (RoHS & no Sb/Br)"
U8: library part CMP-0075392-3, "175-W Stereo, 350-W Mono Ultra-HD Digital-Input Class-D Amplifier with Advanced DSP Processing, DKQ0056A (SSOP-56)"
U9 U11 U13 U14 U31: "Single 2-Line to 1-Line Data Selector Multiplexer, DCT0008A (SSOP-8)"
U10: "High Voltage 1A Step Down Switching Regulator, 10-pin LLP, Pb-Free"
U12: "MIXED SIGNAL MICROCONTROLLER, RHA0040B (VQFN-40)"
U15: "1A Low Dropout Regulator, 4-pin SOT-223, Pb-Free"
U16: "Buck Step Down Regulator with 3 to 17 V Input and 5 V Output, -40 to 85 degC, 8-Pin WSON (DSG), Green (RoHS & no Sb/Br)"
U17: library part CMP-0073732-2, "Dual, 1-A, Low Noise (3.8-uVRMS), LDO Voltage Regulator, RTJ0020D (WQFN-20)"
U18 U19 U20 U21 U22 U23 U24 U25: library part SN74LVC1G125DSFR, "Single Bus Buffer Gate With 3-State Output, DSF0006A (X2SON-6)"
U26: "Programmable 1-PLL VCXO Clock Synthesizer With 1.8-V, 2.5-V, and 3.3-V Outputs, PW0014A (TSSOP-14)"
U27 U28: library part SN74LVC1G14DRLR, "SINGLE SCHMITT-TRIGGER INVERTER, DRL0005A (SOT-5)"
U29: "DUAL BUFFER/DRIVER WITH OPEN DRAIN OUTPUTS, DSF0006A"
U30: "Single-Channel, Adjustable Supervisory Circuit in Ultra-Small Package, DRY0006A (USON-6)"
Y1: "OSC, 24 MHz, 2.25 - 3.63 V, SMD"
Y2: "OSC, 24.576 MHz, 2.25 - 3.63 V, SMD"
Y3: "Oscillators, 22.5792MHz, CMOS, 3.3V, SMD"
ZZ1 ZZ2 ZZ3: library part AssemblyNote

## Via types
v1: diameter 0.635, hole 0.254, Top Layer to Bottom Layer, tented both sides, 653 vias
v2: diameter 0.508, hole 0.254, Top Layer to Bottom Layer, tented both sides, 340 vias
v3: diameter 0.5, hole 0.2, Top Layer to Bottom Layer, 24 vias
v4: diameter 0.6, hole 0.3, Top Layer to Bottom Layer, 12 vias
v5: diameter 0.762, hole 0.254, Top Layer to Bottom Layer, tented both sides, 8 vias
v6: diameter 0.457, hole 0.203, Top Layer to Bottom Layer, tented both sides, 4 vias

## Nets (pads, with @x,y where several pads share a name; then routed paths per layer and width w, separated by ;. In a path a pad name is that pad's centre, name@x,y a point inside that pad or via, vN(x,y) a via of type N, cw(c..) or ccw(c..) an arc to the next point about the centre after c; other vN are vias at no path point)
1.0V: C125.1 C126.1 C127.2 C128.2 C129.2 C130.2 C131.2 C132.2 C133.2 C134.2 C135.2 C136.2 C137.2 C138.2 C139.2 C140.2 L1.2 R1.2 R2.2 R140.1 R156.1 U1.4 U2.11 U2.16 U2.17 U2.24 U2.36 U2.41 U2.49 U2.56 U2.60 U2.73 U2.80 U2.81 U2.87 U2.101 U2.102 U2.120 U2.126 | length 126.8
  Top Layer w0.2: v1(2.5,85) 4.25,83.25 v2(6.875,83.25) ; C128.2@4.125,111.5 4.175,111.55 v2(4.875,111.55) ; C129.2@4.125,113.625 4.2,113.55 v2(4.875,113.55) ; C130.2@4.125,116.75 v2(4.875,116.75) ; v2@5.875,107.35 v2(5.85,107.375) 5.85,108.1 C140.2@5.875,108.125 ; v2(5.875,120.125) C135.2@5.875,120.875 ; C139.2@8.25,106.5 v2(8.25,107.375) ; v2(11.45,120.125) 11.45,119.3 C133.2@11.5,119.25 ; C131.2@14.25,119.25 v2(14.25,120.125) ; v2(15.45,107.375) 15.45,106.55 C138.2@15.5,106.5 ; v2(15.85,120.125) 15.85,119.275 C132.2@15.875,119.25 ; v2(17.625,111.15) 18.35,111.15 C137.2@18.375,111.125 ; v2(17.625,113.55) 18.3,113.55 C136.2@18.375,113.625 ; v2(17.625,116.75) C127.2@18.375,116.75
  Top Layer w0.25: v2(7.875,120.125) C134.2@7.875,120.875
  Top Layer w0.5: v2(4.875,116.75) 5.875,117.75 v2(5.875,120.125) v2(7.875,120.125)
  Signal Layer 2 w0.2: v1(2.5,85) 2.5,96.875 2.375,97 2.375,103.625 3.75,105 7.125,105 8.25,106.125 v2(8.25,107.375)
  Signal Layer 2 w0.5: v2(4.875,111.55) 6.8,111.55 7,111.75 ; v2(4.875,113.55) 6.95,113.55 7,113.5 7,114.625 v2(4.875,116.75) ; v2(5.85,107.375) 5.85,109.475 7.5,111.125 ; v2(8.25,107.375) 8.5,107.625 8.5,110.25 ; 14.25,118.75 v2(14.25,120.125) ; 15.375,110.375 15.438,110.312 15.45,110.3 v2(15.45,107.375) 15.45,106.05 17.25,104.25 v1(18.625,104.25) ; v2(15.85,120.125) 15.85,118.9 16,118.75 ; 16,113.5 16.05,113.55 v2(17.625,113.55)
  Signal Layer 2 w0.75: 7,113.5 7,111.75 8.5,110.25 15.375,110.25 15.438,110.312 16,110.875 16,113.5 16,115.75 17,116.75 v2(17.625,116.75) 17.625,117.625 16.5,118.75 16,118.75 14.25,118.75 12,118.75 11.45,119.3 v2(11.45,120.125)
  Bottom Layer w0.2: U2.11@3.55,111.55 v2(4.875,111.55) ; U2.16@3.55,113.55 U2.17@3.55,113.95 ; U2.24@3.55,116.75 v2(4.875,116.75) ; U2.16@3.625,113.55 v2(4.875,113.55) ; U2.126@5.85,106.05 v2(5.85,107.375) ; v2(5.875,120.125) 6.25,120.5 U2.36@6.25,121.45 ; v2(6.875,83.25) R156.1@7.795,83.25 ; v2(7.875,120.125) 8.25,120.5 U2.41@8.25,121.45 ; U2.120@8.25,106.05 v2(8.25,107.375) ; v2(11.45,120.125) U2.49@11.45,121.45 ; v2(14.25,120.125) U2.56@14.25,121.45 ; U2.102@15.45,106.05 15.8,106.05 U2.101@15.85,106 ; U2.102@15.45,106.125 v2(15.45,107.375) ; v2(15.85,120.125) U2.60@15.85,121.45 ; R140.1@17.5,104.05 R140.1@17.7,104.25 v1(18.625,104.25) ; v2(17.625,111.15) U2.87@18.95,111.15 ; v2(17.625,113.55) U2.81@18.95,113.55 U2.80@18.95,113.95 ; v2(17.625,116.75) U2.73@18.95,116.75
  other v1: 25.25,110 25.25,110.875 25.25,111.875
1.8V: C3.1 C89.2 C146.2 C147.2 R8.1 U6.8 U7.17 U17.11 U17.12 U26.3 | length 50.5
  Top Layer w0.25: v2(5.25,102.875) 5.875,102.875 C146.2@6,102.75 ; v5(46.75,101.75) C89.2@47.5,101.75
  Top Layer w0.5: v1(21.625,100.75) 23,100.75 24.25,99.5 v1(37.5,99.5)
  Signal Layer 2 w0.5: v2(5.25,102.875) 7.5,102.875 v2(7.875,102.5) 10.625,99.75 20.625,99.75 v1(21.625,100.75) ; v1(37.5,99.5) 37.875,99.875 44.875,99.875 v5(46.75,101.75)
  Bottom Layer w0.25: v2(5.25,102.875) U6.8@5.875,102.875 ; U26.3@7.6,100.45 7.6,101.75 C147.2@7.625,101.75 7.625,102.25 v2(7.875,102.5) ; v5(46.75,101.75) U7.17@48.225,101.75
